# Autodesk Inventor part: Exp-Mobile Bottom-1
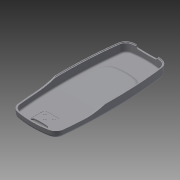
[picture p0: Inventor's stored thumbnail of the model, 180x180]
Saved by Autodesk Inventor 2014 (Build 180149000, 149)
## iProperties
Created: 2011-02
Part Number: Exp-Mobile Bottom-1
Material: Generic
Document SubType Name: Modeling
Designer: gaom
Density: 1 g/cm^3
Appearance: Default
Translation Standard: STEP AP214IS
FileName: C:\Users\gaom\Desktop\Tutorial-2\Exp-Mobile Bottom.stp
PreProcessor: Autodesk Inventor 2012
PostProcessor: Build: 152, Release: 2012 RTM - Date: Tue 02/08/2011
Sent Units: millimeter
Uncertainty: 0.01
Author: gaom
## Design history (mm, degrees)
node "Exp-Mobile Bottom1"
body "Solid1"
node "Base1"
